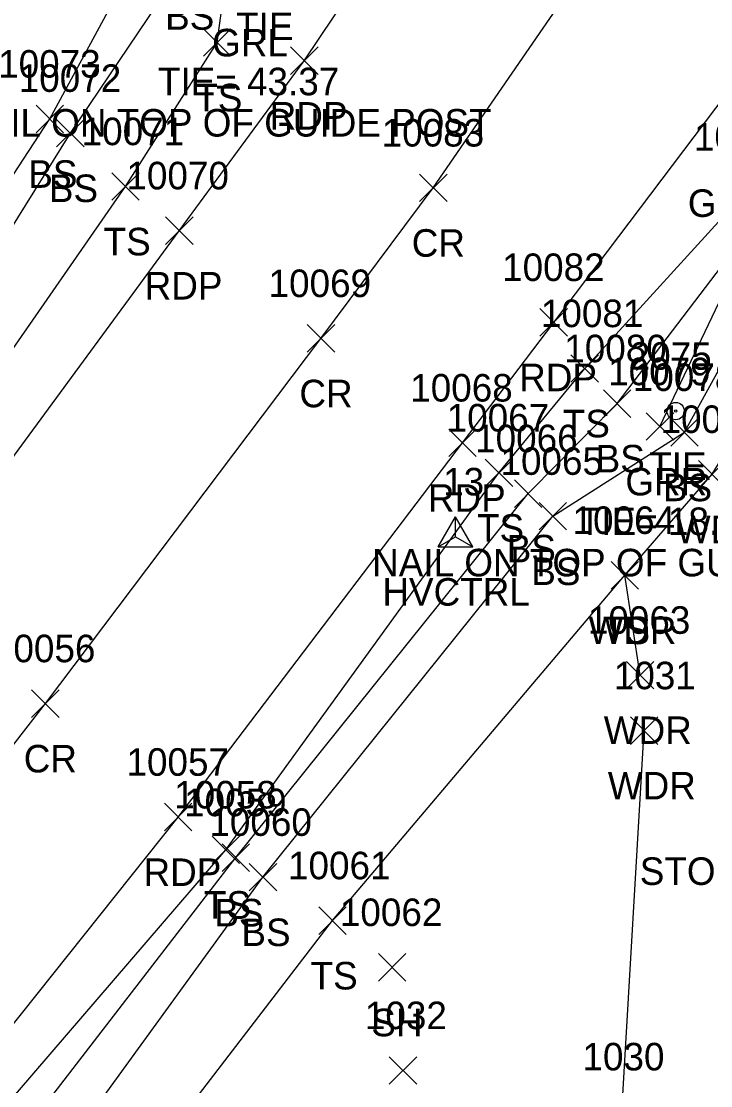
# Model space of a CAD drawing. Extents: x 1651685 to 1653558, y 889533 to 891085.
# Drawn here: x 1652635.2 to 1652685.2, y 890137.3 to 890214.6 of the extents above; entities that cross this region are included whole.
import ezdxf

# ---------------------------------------------------------------- set-up
doc = ezdxf.new("R2010")
doc.units = 0
for name, color, linetype in [('C_A', 7, 'Continuous'), ('C_C', 7, 'Continuous'), ('C_I', 7, 'Continuous'), ('CBP', 7, 'Continuous'), ('CPSM', 7, 'Continuous'), ('L_A', 7, 'Continuous'), ('L_C', 7, 'Continuous'), ('L_I', 7, 'Continuous'), ('L_TIC', 7, 'Continuous'), ('LAWA', 7, 'Continuous'), ('LELB', 7, 'Continuous'), ('P_A', 7, 'Continuous'), ('P_I', 7, 'Continuous'), ('P_TIC', 7, 'Continuous'), ('PET', 7, 'Continuous'), ('PRC', 7, 'Continuous'), ('R_A', 7, 'Continuous'), ('R_I', 7, 'Continuous'), ('R_TIC', 7, 'Continuous'), ('RGR', 7, 'Continuous')]:
    doc.layers.add(name, color=color, linetype=linetype)

msp = doc.modelspace()

# ---------------------------------------------------------------- linework, layer by layer
at = {"layer": 'CBP'}
for radius in [0.625, 0.0833]:
    msp.add_circle((1652682.69, 890186.318), radius, dxfattribs=at)
at = {"layer": 'CPSM'}
for p, q in [((1652665.468, 890176.473), (1652666.718, 890178.638)), ((1652667.968, 890176.473), (1652666.718, 890178.638)), ((1652666.718, 890177.194), (1652666.718, 890178.638)), ((1652665.468, 890176.473), (1652666.718, 890177.194)), ((1652666.718, 890177.194), (1652666.718, 890177.194)), ((1652666.718, 890177.194), (1652667.968, 890176.473)), ((1652665.468, 890176.473), (1652667.968, 890176.473))]:
    msp.add_line(p, q, dxfattribs=at)
at = {"layer": 'L_TIC'}
for points in [[(1652648.427, 890212.078), (1652650.427, 890214.078)], [(1652650.427, 890212.078), (1652648.427, 890214.078)], [(1652636.283, 890206.525), (1652638.283, 890208.525)], [(1652638.283, 890206.525), (1652636.283, 890208.525)], [(1652637.777, 890205.491), (1652639.777, 890207.491)], [(1652639.777, 890205.491), (1652637.777, 890207.491)], [(1652641.777, 890201.622), (1652643.777, 890203.622)], [(1652643.777, 890201.622), (1652641.777, 890203.622)], [(1652675.091, 890188.411), (1652677.091, 890190.411)], [(1652677.091, 890188.411), (1652675.091, 890190.411)], [(1652677.44, 890185.862), (1652679.44, 890187.862)], [(1652679.44, 890185.862), (1652677.44, 890187.862)], [(1652682.325, 890183.776), (1652684.325, 890185.776)], [(1652684.325, 890183.776), (1652682.325, 890185.776)], [(1652668.869, 890180.835), (1652670.869, 890182.835)], [(1652670.869, 890180.835), (1652668.869, 890182.835)], [(1652684.338, 890180.728), (1652686.338, 890182.728)], [(1652686.338, 890180.728), (1652684.338, 890182.728)], [(1652670.989, 890179.33), (1652672.989, 890181.33)], [(1652672.989, 890179.33), (1652670.989, 890181.33)], [(1652672.773, 890177.689), (1652674.773, 890179.689)], [(1652674.773, 890177.689), (1652672.773, 890179.689)], [(1652678.001, 890173.399), (1652680.001, 890175.399)], [(1652680.001, 890173.399), (1652678.001, 890175.399)], [(1652678.001, 890173.399), (1652680.001, 890175.399)], [(1652680.001, 890173.399), (1652678.001, 890175.399)], [(1652679.109, 890166.148), (1652681.109, 890168.148)], [(1652681.109, 890166.148), (1652679.109, 890168.148)], [(1652679.403, 890162.124), (1652681.403, 890164.124)], [(1652681.403, 890162.124), (1652679.403, 890164.124)], [(1652649.057, 890153.468), (1652651.057, 890155.468)], [(1652651.057, 890153.468), (1652649.057, 890155.468)], [(1652649.778, 890152.905), (1652651.778, 890154.905)], [(1652651.778, 890152.905), (1652649.778, 890154.905)], [(1652651.742, 890151.479), (1652653.742, 890153.479)], [(1652653.742, 890151.479), (1652651.742, 890153.479)], [(1652656.793, 890148.33), (1652658.793, 890150.33)], [(1652658.793, 890148.33), (1652656.793, 890150.33)], [(1652661.121, 890144.933), (1652663.121, 890146.933)], [(1652663.121, 890144.933), (1652661.121, 890146.933)], [(1652661.91, 890137.448), (1652663.91, 890139.448)], [(1652663.91, 890137.448), (1652661.91, 890139.448)]]:
    msp.add_lwpolyline(points, dxfattribs=at)
at = {"layer": 'LAWA'}
for points in [[(1652680.109, 890167.148), (1652679.001, 890174.399), (1652685.338, 890181.728), (1652695.334, 890198.043), (1652694.159, 890203.394), (1652698.388, 890207.793), (1652703.573, 890213.567)], [(1652552.288, 889965.957), (1652571.673, 889995.454), (1652586.672, 890018.83), (1652616.646, 890057.034), (1652642.237, 890083.822), (1652665.447, 890109.508), (1652678.783, 890135.452), (1652680.403, 890163.124)]]:
    msp.add_lwpolyline(points, dxfattribs=at)
at = {"layer": 'LELB'}
for points in [[(1652293.22, 889915.657), (1652303.087, 889907.933), (1652317.352, 889908.787), (1652320.692, 889910.303), (1652331.925, 889916.218), (1652367.247, 889934.931), (1652401.811, 889955.303), (1652430.737, 889974.749), (1652457.461, 889995.306), (1652485.921, 890020.39), (1652507.159, 890038.538), (1652516.287, 890046.898), (1652543.454, 890076.686), (1652569.753, 890105.322), (1652598.993, 890142.549), (1652623.843, 890175.329), (1652642.777, 890202.622), (1652649.427, 890213.078), (1652650.337, 890219.795), (1652662.296, 890235.675), (1652673.049, 890250.912), (1652676.633, 890257.992), (1652674.277, 890264.417)], [(1652541.966, 890077.829), (1652566.603, 890107.883), (1652595.779, 890145.784), (1652618.656, 890179.028), (1652637.283, 890207.525), (1652644.338, 890220.613), (1652656.915, 890239.723), (1652667.365, 890255.047), (1652670.051, 890260.475)], [(1652348.147, 889927.343), (1652366.557, 889935.991), (1652400.402, 889956.703), (1652430.052, 889976.641), (1652456.701, 889996.321), (1652485.07, 890021.636), (1652505.874, 890039.823), (1652515.189, 890048.17), (1652541.966, 890077.829), (1652568.76, 890106.071), (1652597.371, 890144.264), (1652620.769, 890177.545), (1652638.777, 890206.491), (1652647.207, 890218.999), (1652658.7, 890237.833), (1652668.915, 890254.325), (1652671.688, 890259.267)], [(1652059.958, 889769.148), (1652077.097, 889776.338), (1652118.687, 889793.555), (1652148.832, 889805.136), (1652195.565, 889824.702), (1652235.22, 889839.021), (1652273.168, 889851.707), (1652312.186, 889868.505), (1652346.463, 889887.35), (1652384.438, 889904.888), (1652418.627, 889927.641), (1652449.257, 889948.785), (1652484.179, 889973.177), (1652505.899, 889994.659), (1652536.895, 890025.511), (1652566.282, 890055.689), (1652594.629, 890083.579), (1652622.175, 890122.044), (1652650.057, 890154.468), (1652669.869, 890181.835), (1652676.091, 890189.411), (1652687.771, 890202.227), (1652700.091, 890224.174)], [(1652510.075, 889988.608), (1652541.256, 890021.657), (1652570.449, 890051.196), (1652599.255, 890080.662), (1652627.515, 890117.732), (1652652.742, 890152.479), (1652673.773, 890178.689), (1652683.325, 890184.776), (1652690.804, 890198.36), (1652694.159, 890203.394)], [(1652425.64, 889918.847), (1652456.726, 889936.262), (1652476.981, 889952.39), (1652484.779, 889967.501), (1652507.93, 889991.53), (1652539.732, 890022.766), (1652568.751, 890053.154), (1652596.439, 890082.379), (1652624.715, 890120.116), (1652650.778, 890153.905), (1652671.989, 890180.33), (1652678.44, 890186.862), (1652688.877, 890200.577)], [(1652511.691, 889985.78), (1652544.244, 890018.707), (1652572.567, 890047.754), (1652604.473, 890076.616), (1652630.903, 890114.293), (1652657.793, 890149.33), (1652679.001, 890174.399)]]:
    msp.add_lwpolyline(points, dxfattribs=at)
at = {"layer": 'P_TIC'}
for points in [[(1652654.748, 890210.753), (1652656.748, 890212.753)], [(1652656.748, 890210.753), (1652654.748, 890212.753)], [(1652664.106, 890201.523), (1652666.106, 890203.523)], [(1652666.106, 890201.523), (1652664.106, 890203.523)], [(1652645.677, 890198.415), (1652647.677, 890200.415)], [(1652647.677, 890198.415), (1652645.677, 890200.415)], [(1652672.844, 890191.76), (1652674.844, 890193.76)], [(1652674.844, 890191.76), (1652672.844, 890193.76)], [(1652655.957, 890190.595), (1652657.957, 890192.595)], [(1652657.957, 890190.595), (1652655.957, 890192.595)], [(1652666.225, 890183.01), (1652668.225, 890185.01)], [(1652668.225, 890183.01), (1652666.225, 890185.01)], [(1652635.96, 890164.085), (1652637.96, 890166.085)], [(1652637.96, 890164.085), (1652635.96, 890166.085)], [(1652645.593, 890155.843), (1652647.593, 890157.843)], [(1652647.593, 890155.843), (1652645.593, 890157.843)]]:
    msp.add_lwpolyline(points, dxfattribs=at)
at = {"layer": 'PET'}
for points in [[(1652310.071, 889873.858), (1652345.018, 889890.876), (1652381.133, 889910.269), (1652416.225, 889931.732), (1652447.247, 889952.285), (1652474.07, 889972.993), (1652503.702, 889997.944), (1652534.457, 890027.787), (1652563.385, 890057.924), (1652590.108, 890087.923), (1652620.326, 890123.876), (1652646.593, 890156.843), (1652667.225, 890184.01), (1652673.844, 890192.76), (1652698.186, 890224.989), (1652707.052, 890238.801), (1652697.139, 890249.857), (1652688.173, 890260.372)], [(1652333.651, 889912.667), (1652369.12, 889931.534), (1652403.155, 889952.408), (1652433.06, 889972.257), (1652459.319, 889992.677), (1652488.38, 890016.936), (1652517.957, 890045.24), (1652545.959, 890074.028), (1652572.077, 890103.378), (1652602.102, 890139.625), (1652627.16, 890172.833), (1652646.677, 890199.415), (1652655.748, 890211.753), (1652675.089, 890240.598), (1652688.173, 890260.372)]]:
    msp.add_lwpolyline(points, dxfattribs=at)
at = {"layer": 'PRC'}
msp.add_lwpolyline([(1652339.131, 889902.361), (1652374.757, 889921.453), (1652409.696, 889942.759), (1652439.668, 889962.958), (1652466.375, 889983.158), (1652495.638, 890007.899), (1652525.652, 890036.364), (1652554.01, 890065.879), (1652580.922, 890096.263), (1652611.449, 890132.238), (1652636.96, 890165.085), (1652656.957, 890191.595), (1652665.106, 890202.523), (1652686.512, 890233.671), (1652697.139, 890249.857)], dxfattribs=at)
at = {"layer": 'R_TIC'}
for points in [[(1652680.549, 890184.195), (1652682.549, 890186.195)], [(1652682.549, 890184.195), (1652680.549, 890186.195)]]:
    msp.add_lwpolyline(points, dxfattribs=at)
at = {"layer": 'RGR'}
msp.add_lwpolyline([(1652681.549, 890185.195), (1652688.877, 890200.577), (1652700.091, 890224.174), (1652707.601, 890236.977), (1652707.742, 890237.28)], dxfattribs=at)

# ---------------------------------------------------------------- texts
at = {"layer": 'C_A'}
for s, p in [('TIE', (1652650.797, 890213.246)), ('TIE', (1652680.769, 890181.318)), ('HVCTRL', (1652661.411, 890172.194))]:
    msp.add_text(s, height=2, dxfattribs=at).set_placement(p)
at = {"layer": 'C_C'}
for s, p in [('TIE= 43.37', (1652645.127, 890209.246)), ('NAIL ON TOP OF GUIDE POST', (1652630.695, 890206.246)), ('TIE= 18.39', (1652675.659, 890177.318)), ('NAIL ON TOP OF GUIDE POST', (1652660.667, 890174.318))]:
    msp.add_text(s, height=2, dxfattribs=at).set_placement(p)
at = {"layer": 'C_I'}
for s, p in [('2075', (1652679.351, 890189.318)), ('13', (1652665.82, 890180.194))]:
    msp.add_text(s, height=2, dxfattribs=at).set_placement(p)
at = {"layer": 'L_A'}
for s, p in [('BS', (1652645.648, 890213.999)), ('TS', (1652647.837, 890208.078)), ('BS', (1652635.724, 890202.525)), ('BS', (1652637.218, 890201.491)), ('TS', (1652641.187, 890197.622)), ('TS', (1652674.5, 890184.411)), ('BS', (1652676.881, 890181.862)), ('BS', (1652681.766, 890179.776)), ('TS', (1652668.278, 890176.835)), ('WDR', (1652682.7, 890176.728)), ('BS', (1652670.43, 890175.33)), ('BS', (1652672.214, 890173.689)), ('WDR', (1652676.364, 890169.399)), ('TS', (1652677.411, 890169.399)), ('WDR', (1652677.471, 890162.148)), ('WDR', (1652677.765, 890158.124)), ('TS', (1652648.467, 890149.468)), ('BS', (1652649.219, 890148.905)), ('BS', (1652651.183, 890147.479)), ('TS', (1652656.203, 890144.33)), ('SH', (1652660.609, 890140.933))]:
    msp.add_text(s, height=2, dxfattribs=at).set_placement(p)
at = {"layer": 'L_C'}
for s, p in [('GRANITE BLOCK RETAINING', (1652683.57, 890200.412)), ('STONE RETAINING', (1652680.083, 890151.919))]:
    msp.add_text(s, height=2, dxfattribs=at).set_placement(p)
at = {"layer": 'L_I'}
for s, p in [('10073', (1652633.536, 890210.525)), ('10072', (1652635.029, 890209.491)), ('10071', (1652639.596, 890205.622)), ('10089', (1652684.015, 890205.227)), ('10081', (1652672.91, 890192.411)), ('10080', (1652674.606, 890189.862)), ('10078', (1652679.577, 890187.776)), ('10067', (1652666.074, 890184.835)), ('10077', (1652681.59, 890184.728)), ('10066', (1652668.138, 890183.33)), ('10065', (1652669.978, 890181.689)), ('10064', (1652675.206, 890177.399)), ('10064', (1652675.206, 890177.399)), ('10063', (1652676.313, 890170.148)), ('1031', (1652678.198, 890166.124)), ('10058', (1652646.309, 890157.468)), ('10059', (1652647.023, 890156.905)), ('10060', (1652648.86, 890155.479)), ('10061', (1652654.565, 890152.33)), ('10062', (1652658.326, 890148.933)), ('1032', (1652660.139, 890141.448)), ('1030', (1652675.925, 890138.452))]:
    msp.add_text(s, height=2, dxfattribs=at).set_placement(p)
at = {"layer": 'P_A'}
for s, p in [('RDP', (1652653.236, 890206.753)), ('CR', (1652663.539, 890197.523)), ('RDP', (1652644.165, 890194.415)), ('RDP', (1652671.333, 890187.76)), ('CR', (1652655.39, 890186.595)), ('RDP', (1652664.713, 890179.01)), ('CR', (1652635.393, 890160.085)), ('RDP', (1652644.082, 890151.843))]:
    msp.add_text(s, height=2, dxfattribs=at).set_placement(p)
at = {"layer": 'P_I'}
for s, p in [('10083', (1652661.358, 890205.523)), ('10070', (1652642.842, 890202.415)), ('10082', (1652670.097, 890195.76)), ('10069', (1652653.154, 890194.595)), ('10068', (1652663.43, 890187.01)), ('10056', (1652633.157, 890168.085)), ('10057', (1652642.846, 890159.843))]:
    msp.add_text(s, height=2, dxfattribs=at).set_placement(p)
at = {"layer": 'R_A'}
for s, p in [('GRL', (1652649.061, 890212.067)), ('GRR', (1652679.037, 890180.195))]:
    msp.add_text(s, height=2, dxfattribs=at).set_placement(p)
at = {"layer": 'R_I'}
msp.add_text('10079', height=2, dxfattribs=at).set_placement((1652677.793, 890188.195))

doc.saveas('drawing.dxf')
